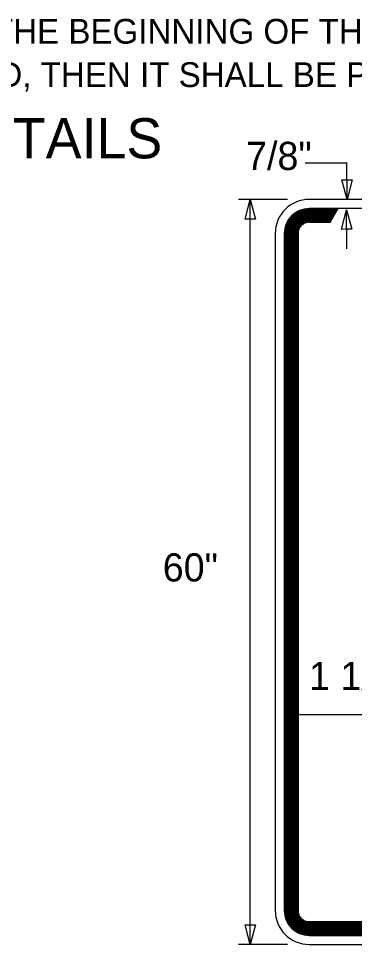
# Model space of a CAD drawing. Extents: x 15261 to 18126, y 1908 to 6555.
# Drawn here: x 17744.9 to 17845.2, y 2373.6 to 2649.8 of the extents above; entities that cross this region are included whole.
import ezdxf

# ---------------------------------------------------------------- set-up
doc = ezdxf.new("R2010")
doc.units = 0
doc.layers.add('TYPICAL_EX', color=7, linetype='Continuous')
doc.layers.add('TYPICAL_TEXT_DIMEN_PR', color=7, linetype='Continuous')

msp = doc.modelspace()

# ---------------------------------------------------------------- linework, layer by layer
at = {"layer": 'TYPICAL_EX'}
for p, q in [((17974.24, 2595.85), (17831.73, 2595.85)), ((17840.43, 2593.13), (17831.73, 2593.13)), ((17840.36, 2593.02), (17831.73, 2593.02)), ((17840.3, 2592.91), (17831.73, 2592.91)), ((17840.23, 2592.8), (17831.73, 2592.8)), ((17840.17, 2592.68), (17831.73, 2592.68)), ((17840.1, 2592.57), (17831.73, 2592.57)), ((17840.04, 2592.46), (17831.73, 2592.46)), ((17839.97, 2592.35), (17831.73, 2592.35)), ((17839.91, 2592.24), (17831.73, 2592.24)), ((17839.85, 2592.12), (17831.73, 2592.12)), ((17839.78, 2592.01), (17831.73, 2592.01)), ((17839.72, 2591.9), (17831.73, 2591.9)), ((17839.65, 2591.79), (17831.73, 2591.79)), ((17839.59, 2591.67), (17831.73, 2591.67)), ((17844.36, 2593.13), (17840.35, 2593.13)), ((17974.24, 2593.13), (17844.36, 2593.13)), ((17839.52, 2591.56), (17831.73, 2591.56)), ((17839.46, 2591.45), (17831.73, 2591.45)), ((17839.39, 2591.34), (17831.73, 2591.34)), ((17839.33, 2591.23), (17831.73, 2591.23)), ((17839.26, 2591.11), (17831.73, 2591.11)), ((17839.2, 2591), (17831.73, 2591)), ((17839.14, 2590.89), (17831.73, 2590.89)), ((17839.07, 2590.78), (17831.73, 2590.78)), ((17839.01, 2590.67), (17831.73, 2590.67)), ((17838.94, 2590.55), (17831.73, 2590.55)), ((17838.88, 2590.44), (17831.73, 2590.44)), ((17838.81, 2590.33), (17831.73, 2590.33)), ((17838.75, 2590.22), (17831.73, 2590.22)), ((17838.68, 2590.11), (17831.73, 2590.11)), ((17838.62, 2589.99), (17831.73, 2589.99)), ((17838.55, 2589.88), (17831.73, 2589.88)), ((17838.49, 2589.77), (17831.73, 2589.77)), ((17838.42, 2589.66), (17831.73, 2589.66)), ((17838.36, 2589.55), (17831.73, 2589.55)), ((17838.3, 2589.43), (17831.73, 2589.43)), ((17838.23, 2589.32), (17831.73, 2589.32)), ((17838.17, 2589.21), (17831.73, 2589.21)), ((17838.1, 2589.1), (17831.73, 2589.1)), ((17838.06, 2589.02), (17831.73, 2589.02)), ((17821.55, 2585.67), (17821.55, 2437.58)), ((17824.27, 2585.67), (17824.27, 2437.58)), ((17824.38, 2585.67), (17824.38, 2437.58)), ((17824.49, 2585.67), (17824.49, 2437.58)), ((17824.6, 2585.67), (17824.6, 2437.58)), ((17824.71, 2585.67), (17824.71, 2437.45)), ((17824.83, 2585.67), (17824.83, 2437.58)), ((17824.94, 2585.67), (17824.94, 2437.58)), ((17825.05, 2585.67), (17825.05, 2437.55)), ((17825.16, 2585.67), (17825.16, 2437.59)), ((17825.27, 2585.67), (17825.27, 2437.53)), ((17825.39, 2585.67), (17825.39, 2437.57)), ((17825.5, 2585.67), (17825.5, 2437.58)), ((17825.61, 2585.67), (17825.61, 2437.62)), ((17825.72, 2585.67), (17825.72, 2437.58)), ((17825.83, 2585.67), (17825.83, 2437.58)), ((17825.95, 2585.67), (17825.95, 2437.58)), ((17826.06, 2585.67), (17826.06, 2437.58)), ((17826.17, 2585.67), (17826.17, 2437.58)), ((17826.28, 2585.67), (17826.28, 2437.57)), ((17826.4, 2585.67), (17826.4, 2437.58)), ((17826.51, 2585.67), (17826.51, 2437.59)), ((17826.62, 2585.67), (17826.62, 2437.58)), ((17826.73, 2585.67), (17826.73, 2437.58)), ((17826.84, 2585.67), (17826.84, 2437.56)), ((17826.96, 2585.67), (17826.96, 2437.6)), ((17827.07, 2585.67), (17827.07, 2437.58)), ((17827.18, 2585.67), (17827.18, 2437.58)), ((17827.29, 2585.67), (17827.29, 2456.28)), ((17827.4, 2585.67), (17827.4, 2456.28)), ((17827.51, 2585.67), (17827.51, 2456.28)), ((17827.63, 2585.67), (17827.63, 2437.57)), ((17827.74, 2585.67), (17827.74, 2437.56)), ((17827.85, 2585.67), (17827.85, 2437.58)), ((17827.96, 2585.67), (17827.96, 2437.57)), ((17828.08, 2585.67), (17828.08, 2437.57)), ((17828.19, 2585.67), (17828.19, 2437.6)), ((17828.3, 2585.67), (17828.3, 2437.59)), ((17828.38, 2585.67), (17828.38, 2437.6)), ((17827.29, 2456.35), (17827.29, 2383.73)), ((17827.4, 2456.28), (17827.4, 2383.73)), ((17827.51, 2456.28), (17827.51, 2383.73)), ((17828.79, 2442.14), (17977.54, 2442.14)), ((17821.55, 2437.58), (17821.55, 2383.73)), ((17824.27, 2437.58), (17824.27, 2383.73)), ((17824.38, 2437.58), (17824.38, 2383.73)), ((17824.49, 2437.58), (17824.49, 2383.73)), ((17824.6, 2437.58), (17824.6, 2383.73)), ((17824.71, 2437.58), (17824.71, 2383.73)), ((17824.83, 2437.58), (17824.83, 2383.73)), ((17824.94, 2437.58), (17824.94, 2383.73)), ((17825.05, 2437.58), (17825.05, 2383.06)), ((17825.16, 2437.58), (17825.16, 2383.73)), ((17825.27, 2437.58), (17825.27, 2383.73)), ((17825.39, 2437.58), (17825.39, 2383.73)), ((17825.5, 2437.58), (17825.5, 2383.73)), ((17825.61, 2437.63), (17825.61, 2383.73)), ((17825.72, 2437.58), (17825.72, 2383.73)), ((17825.83, 2437.58), (17825.83, 2383.73)), ((17825.95, 2437.58), (17825.95, 2383.73)), ((17826.06, 2437.58), (17826.06, 2383.73)), ((17826.17, 2437.58), (17826.17, 2383.73)), ((17826.28, 2437.58), (17826.28, 2383.73)), ((17826.4, 2437.58), (17826.4, 2383.73)), ((17826.51, 2437.58), (17826.51, 2383.73)), ((17826.62, 2437.58), (17826.62, 2383.73)), ((17826.73, 2437.58), (17826.73, 2383.73)), ((17826.84, 2437.58), (17826.84, 2383.73)), ((17826.96, 2437.58), (17826.96, 2383.73)), ((17827.07, 2437.58), (17827.07, 2383.73)), ((17827.18, 2437.58), (17827.18, 2383.73)), ((17827.63, 2437.58), (17827.63, 2383.73)), ((17827.74, 2437.58), (17827.74, 2383.73)), ((17827.85, 2437.58), (17827.85, 2383.73)), ((17827.96, 2437.57), (17827.96, 2383.73)), ((17828.08, 2437.58), (17828.08, 2383.73)), ((17828.19, 2437.58), (17828.19, 2383.73)), ((17828.3, 2437.58), (17828.3, 2383.73)), ((17828.38, 2437.58), (17828.38, 2383.73)), ((17831.73, 2380.38), (17974.24, 2380.38)), ((17831.73, 2380.3), (17974.24, 2380.3)), ((17831.73, 2380.19), (17974.24, 2380.19)), ((17831.73, 2380.08), (17974.24, 2380.08)), ((17831.73, 2379.97), (17974.24, 2379.97)), ((17831.73, 2379.85), (17974.24, 2379.85)), ((17831.73, 2379.74), (17974.24, 2379.74)), ((17831.73, 2379.63), (17974.24, 2379.63)), ((17831.73, 2379.52), (17974.24, 2379.52)), ((17831.73, 2379.41), (17974.24, 2379.41)), ((17831.73, 2379.29), (17974.24, 2379.29)), ((17831.73, 2379.18), (17974.24, 2379.18)), ((17831.73, 2379.07), (17974.24, 2379.07)), ((17831.73, 2378.96), (17974.24, 2378.96)), ((17831.73, 2378.84), (17974.24, 2378.84)), ((17831.73, 2378.73), (17974.24, 2378.73)), ((17831.73, 2378.62), (17974.24, 2378.62)), ((17831.73, 2378.51), (17974.24, 2378.51)), ((17831.73, 2378.4), (17974.24, 2378.4)), ((17831.73, 2378.28), (17974.24, 2378.28)), ((17831.73, 2378.17), (17974.24, 2378.17)), ((17831.73, 2378.06), (17974.24, 2378.06)), ((17831.73, 2377.95), (17974.24, 2377.95)), ((17831.73, 2377.84), (17974.24, 2377.84)), ((17831.73, 2377.72), (17974.24, 2377.72)), ((17831.73, 2377.61), (17974.24, 2377.61)), ((17831.73, 2377.5), (17974.24, 2377.5)), ((17831.73, 2377.39), (17974.24, 2377.39)), ((17831.73, 2377.28), (17974.24, 2377.28)), ((17831.73, 2377.16), (17974.24, 2377.16)), ((17831.73, 2377.05), (17974.24, 2377.05)), ((17831.73, 2376.94), (17974.24, 2376.94)), ((17831.73, 2376.83), (17974.24, 2376.83)), ((17831.73, 2376.72), (17974.24, 2376.72)), ((17831.73, 2376.6), (17974.24, 2376.6)), ((17831.73, 2376.49), (17974.24, 2376.49)), ((17831.73, 2376.38), (17974.24, 2376.38)), ((17831.73, 2376.27), (17974.24, 2376.27)), ((17831.73, 2373.55), (17974.24, 2373.55))]:
    msp.add_line(p, q, dxfattribs=at)
for centre, radius, start, end in [((17831.73, 2585.67), 10.18, 90, 180), ((17831.73, 2585.67), 7.46, 90, 180), ((17831.73, 2585.67), 7.35, 90, 180), ((17831.73, 2585.67), 7.24, 90, 180), ((17831.73, 2585.67), 7.13, 90, 180), ((17831.73, 2585.67), 7.02, 90, 180), ((17831.73, 2585.67), 6.9, 90, 180), ((17831.73, 2585.67), 6.79, 90, 180), ((17831.73, 2585.67), 6.68, 90, 180), ((17831.73, 2585.67), 6.57, 90, 180), ((17831.73, 2585.67), 6.46, 90, 180), ((17831.73, 2585.67), 6.34, 90, 180), ((17831.73, 2585.67), 6.23, 90, 180), ((17831.73, 2585.67), 6.12, 90, 180), ((17831.73, 2585.67), 6.01, 90, 180), ((17831.73, 2585.67), 5.9, 90, 180), ((17831.73, 2585.67), 5.78, 90, 180), ((17831.73, 2585.67), 5.67, 90, 180), ((17831.73, 2585.67), 5.56, 90, 180), ((17831.73, 2585.67), 5.45, 90, 180), ((17831.73, 2585.67), 5.34, 90, 180), ((17831.73, 2585.67), 5.22, 90, 180), ((17831.73, 2585.67), 5.11, 90, 180), ((17831.73, 2585.67), 5, 90, 180), ((17831.73, 2585.67), 4.89, 90, 180), ((17831.73, 2585.67), 4.78, 90, 180), ((17831.73, 2585.67), 4.66, 90, 180), ((17831.73, 2585.67), 4.55, 90, 180), ((17831.73, 2585.67), 4.44, 90, 180), ((17831.73, 2585.67), 4.33, 90, 180), ((17831.73, 2585.67), 4.21, 90, 180), ((17831.73, 2585.67), 4.1, 90, 180), ((17831.73, 2585.67), 3.99, 90, 180), ((17831.73, 2585.67), 3.88, 90, 180), ((17831.73, 2585.67), 3.77, 90, 180), ((17831.73, 2585.67), 3.65, 90, 180), ((17831.73, 2585.67), 3.54, 90, 180), ((17831.73, 2585.67), 3.43, 90, 180), ((17831.73, 2585.67), 3.36, 90, 180), ((17831.73, 2383.73), 10.18, 180, 270), ((17831.73, 2383.73), 7.46, 180, 270), ((17831.73, 2383.73), 7.35, 180, 270), ((17831.73, 2383.73), 7.24, 180, 270), ((17831.73, 2383.73), 7.13, 180, 270), ((17831.73, 2383.73), 7.02, 180, 270), ((17831.73, 2383.73), 6.9, 180, 270), ((17831.73, 2383.73), 6.79, 180, 270), ((17831.73, 2383.73), 6.68, 180, 270), ((17831.73, 2383.73), 6.57, 180, 270), ((17831.73, 2383.73), 6.46, 180, 270), ((17831.73, 2383.73), 6.34, 180, 270), ((17831.73, 2383.73), 6.23, 180, 270), ((17831.73, 2383.73), 6.12, 180, 270), ((17831.73, 2383.73), 6.01, 180, 270), ((17831.73, 2383.73), 5.9, 180, 270), ((17831.73, 2383.73), 5.78, 180, 270), ((17831.73, 2383.73), 5.67, 180, 270), ((17831.73, 2383.73), 5.56, 180, 270), ((17831.73, 2383.73), 5.45, 180, 270), ((17831.73, 2383.73), 5.34, 180, 270), ((17831.73, 2383.73), 5.22, 180, 270), ((17831.73, 2383.73), 5.11, 180, 270), ((17831.73, 2383.73), 5, 180, 270), ((17831.73, 2383.73), 4.89, 180, 270), ((17831.73, 2383.73), 4.78, 180, 270), ((17831.73, 2383.73), 4.66, 180, 270), ((17831.73, 2383.73), 4.55, 180, 270), ((17831.73, 2383.73), 4.44, 180, 270), ((17831.73, 2383.73), 4.33, 180, 270), ((17831.73, 2383.73), 4.21, 180, 270), ((17831.73, 2383.73), 4.1, 180, 270), ((17831.73, 2383.73), 3.99, 180, 270), ((17831.73, 2383.73), 3.88, 180, 270), ((17831.73, 2383.73), 3.77, 180, 270), ((17831.73, 2383.73), 3.65, 180, 270), ((17831.73, 2383.73), 3.54, 180, 270), ((17831.73, 2383.73), 3.43, 180, 270), ((17831.73, 2383.73), 3.36, 180, 270)]:
    msp.add_arc(centre, radius, start, end, dxfattribs=at)
at = {"layer": 'TYPICAL_TEXT_DIMEN_PR'}
for p, q in [((17830.54, 2606.77), (17842.99, 2606.75)), ((17842.99, 2595.85), (17842.98, 2606.85)), ((17842.99, 2595.85), (17841.41, 2601.71)), ((17841.41, 2601.71), (17842.98, 2601.71)), ((17842.98, 2601.71), (17844.56, 2601.71)), ((17844.56, 2601.71), (17842.99, 2595.85)), ((17825.18, 2595.85), (17810.57, 2595.85)), ((17812.54, 2589.98), (17814.11, 2595.85)), ((17814.11, 2437.58), (17814.11, 2595.85)), ((17814.11, 2595.85), (17815.68, 2589.98)), ((17841.32, 2586.93), (17842.88, 2592.8)), ((17842.91, 2581.08), (17842.88, 2592.8)), ((17842.88, 2592.8), (17844.47, 2586.94)), ((17814.11, 2589.98), (17812.54, 2589.98)), ((17815.68, 2589.98), (17814.11, 2589.98)), ((17842.9, 2586.94), (17841.32, 2586.93)), ((17844.47, 2586.94), (17842.9, 2586.94)), ((17814.11, 2373.55), (17814.11, 2437.58)), ((17814.11, 2373.55), (17812.54, 2379.41)), ((17812.54, 2379.41), (17814.11, 2379.41)), ((17814.11, 2379.41), (17815.68, 2379.41)), ((17815.68, 2379.41), (17814.11, 2373.55)), ((17825.18, 2373.55), (17810.57, 2373.55))]:
    msp.add_line(p, q, dxfattribs=at)

# ---------------------------------------------------------------- texts
for s, height, p in [('THE LIGHTED ARROW PANEL SHALL BE LOCATED AT THE BEGINNING OF THE TAPER AS SHOWN.  WHEN PHYSICAL', 7.392, (17478.58, 2642.34)), ('LIMITATIONS RESTRICT ITS PLACEMENT AS INDICATED, THEN IT SHALL BE PLACED AS CLOSE TO THE BEGINNING', 7.392, (17478.58, 2629.4)), ('SIGN DETAILS', 12, (17677.25, 2608.11)), ('7/8"', 8.4, (17812.86, 2604.65)), ('60"', 8.4, (17787.98, 2481.87)), ('1 1/4"', 8.4, (17831.64, 2449.47))]:
    msp.add_text(s, height=height, dxfattribs=at).set_placement(p)

doc.saveas('drawing.dxf')
